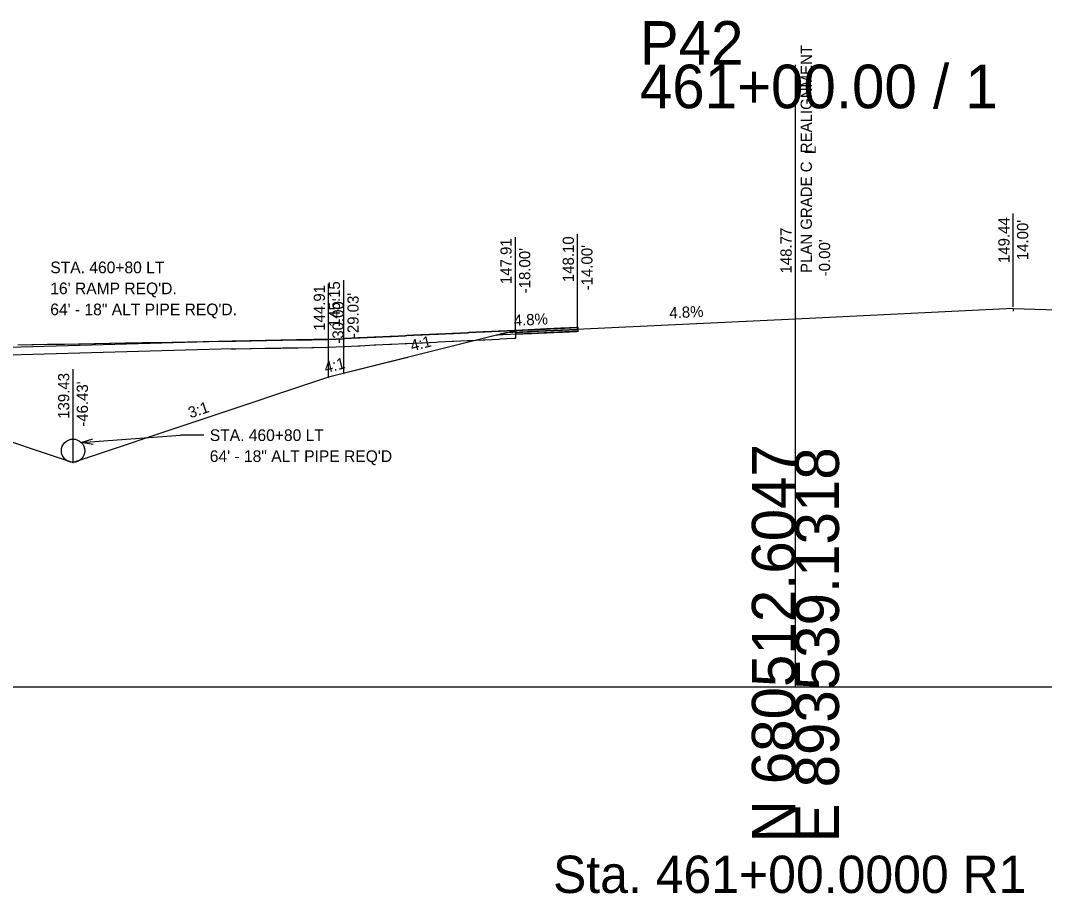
# Model space of a CAD drawing. Extents: x -100 to 4303, y -13 to 10775.
# Drawn here: x 100.2 to 166, y 9486.7 to 9542.8 of the extents above; entities that cross this region are included whole.
import ezdxf

# ---------------------------------------------------------------- set-up
doc = ezdxf.new("R2010")
doc.units = 0
for name, color, linetype in [('_CIVIL_CONSTRUCTION', 7, 'Continuous'), ('ASHPALT_12_5MM1', 7, 'Continuous'), ('CONST_DCH', 7, 'Continuous'), ('CONST_LV3', 7, 'Continuous'), ('Draft_XS_Text', 7, 'Continuous'), ('DTM_P_FINISHED_GRADE', 7, 'Continuous'), ('DTM_TEMP_DROP', 7, 'Continuous'), ('DTM_X_GROUND', 7, 'Continuous'), ('SLOPE_STAKES_FILL', 7, 'Continuous'), ('X_PROFILES_1', 7, 'Continuous'), ('XS_CELL', 7, 'Continuous'), ('XS_P_CRUSHED_STONE', 7, 'Continuous'), ('XS_P_DR_ASPHALT', 7, 'Continuous'), ('XS_P_DR_ASPHALT_B', 7, 'Continuous'), ('XS_P_DR_GRAVEL', 7, 'Continuous'), ('XS_P_DRAINAGE', 7, 'Continuous'), ('XS_P_SHOULDER', 7, 'Continuous'), ('XS_P_TX_CLEARZONE', 7, 'Continuous'), ('XS_P_TX_FS_BS', 7, 'Continuous')]:
    doc.layers.add(name, color=color, linetype=linetype)

msp = doc.modelspace()

# ---------------------------------------------------------------- linework, layer by layer
at = {"layer": 'ASHPALT_12_5MM1'}
for q in [(164, 9524.147), (164, 9524.15)]:
    msp.add_line((164, 9524.317), q, dxfattribs=at)
at = {"layer": 'CONST_LV3'}
for points in [[(100.032, 9521.99), (100.928, 9522.005), (101.032, 9522.007), (101.928, 9522.023), (102.032, 9522.025), (102.928, 9522.04), (103.032, 9522.042), (103.928, 9522.058), (104.032, 9522.06), (104.928, 9522.075), (105.032, 9522.077), (105.928, 9522.093), (106.032, 9522.095), (106.928, 9522.11), (107.032, 9522.112), (107.928, 9522.128), (108.032, 9522.13), (108.928, 9522.145), (109.032, 9522.147), (109.928, 9522.163), (110.032, 9522.165), (110.928, 9522.18), (111.032, 9522.182), (111.928, 9522.198), (112.032, 9522.2), (112.928, 9522.215), (113.032, 9522.217), (113.928, 9522.233), (114.032, 9522.235), (114.928, 9522.25), (115.032, 9522.252), (115.928, 9522.268), (116.032, 9522.27), (116.928, 9522.285), (117.032, 9522.287), (117.928, 9522.303), (118.032, 9522.305), (118.928, 9522.32), (119.032, 9522.322), (119.928, 9522.338), (120.032, 9522.34), (120.928, 9522.383), (121.032, 9522.388), (121.928, 9522.431), (122.032, 9522.436), (122.928, 9522.479), (123.032, 9522.484), (123.928, 9522.527), (124.032, 9522.532), (124.928, 9522.575), (125.032, 9522.58), (125.928, 9522.623), (126.032, 9522.628), (126.928, 9522.671), (127.032, 9522.676), (127.928, 9522.719), (128.032, 9522.724), (128.928, 9522.767), (129.032, 9522.772), (129.928, 9522.815), (130.032, 9522.82), (130.928, 9522.863), (131.032, 9522.868), (131.928, 9522.911), (132.032, 9522.916), (132.928, 9522.959), (133.032, 9522.964), (133.928, 9523.007), (134.032, 9523.012), (134.928, 9523.055), (135.032, 9523.06), (135.928, 9523.103), (136.032, 9523.108)], [(125.084, 9521.177), (120, 9519.906)]]:
    msp.add_lwpolyline(points, dxfattribs=at)
at = {"layer": 'DTM_P_FINISHED_GRADE'}
for points in [[(132.032, 9522.916), (132.928, 9522.959), (133.032, 9522.964), (133.928, 9523.007), (134.032, 9523.012), (134.928, 9523.055), (135.032, 9523.06), (135.928, 9523.103), (136.032, 9523.108)], [(100.032, 9521.99), (100.928, 9522.005), (101.032, 9522.007), (101.928, 9522.023), (102.032, 9522.025), (102.928, 9522.04), (103.032, 9522.042), (103.928, 9522.058), (104.032, 9522.06), (104.928, 9522.075), (105.032, 9522.077), (105.928, 9522.093), (106.032, 9522.095), (106.928, 9522.11), (107.032, 9522.112), (107.928, 9522.128), (108.032, 9522.13), (108.928, 9522.145), (109.032, 9522.147), (109.928, 9522.163), (110.032, 9522.165), (110.928, 9522.18), (111.032, 9522.182), (111.928, 9522.198), (112.032, 9522.2), (112.928, 9522.215), (113.032, 9522.217), (113.928, 9522.233), (114.032, 9522.235), (114.928, 9522.25), (115.032, 9522.252), (115.928, 9522.268), (116.032, 9522.27), (116.928, 9522.285), (117.032, 9522.287), (117.928, 9522.303), (118.032, 9522.305), (118.928, 9522.32), (119.032, 9522.322), (119.928, 9522.338), (120.032, 9522.34), (120.928, 9522.383), (121.032, 9522.388), (121.928, 9522.431), (122.032, 9522.436), (122.928, 9522.479), (123.032, 9522.484), (123.928, 9522.527), (124.032, 9522.532), (124.928, 9522.575), (125.032, 9522.58), (125.928, 9522.623), (126.032, 9522.628), (126.928, 9522.671), (127.032, 9522.676), (127.928, 9522.719), (128.032, 9522.724), (128.928, 9522.767), (129.032, 9522.772), (129.928, 9522.815), (130.032, 9522.82), (130.928, 9522.863), (131.032, 9522.868), (131.928, 9522.911), (132.032, 9522.916)]]:
    msp.add_lwpolyline(points, dxfattribs=at)
at = {"layer": 'DTM_X_GROUND'}
for p, q in [((164, 9524.317), (150.015, 9523.645)), ((164, 9524.317), (168.734, 9524.17)), ((150.015, 9523.645), (131.382, 9522.752))]:
    msp.add_line(p, q, dxfattribs=at)
for points in [[(131.382, 9522.752), (120, 9519.906), (103.57, 9514.43)], [(97.282, 9516.526), (103.57, 9514.43)]]:
    msp.add_lwpolyline(points, dxfattribs=at)
at = {"layer": 'XS_CELL'}
for p, q in [((150, 9500), (150, 9540)), ((150, 9500), (150, 9540)), ((0, 9500), (150, 9500)), ((0, 9500), (150, 9500)), ((150, 9500), (300, 9500)), ((150, 9500), (300, 9500))]:
    msp.add_line(p, q, dxfattribs=at)
at = {"layer": 'XS_P_CRUSHED_STONE'}
for p, q in [((136.032, 9523.108), (134.025, 9523.011)), ((136.032, 9522.817), (136.032, 9523.108)), ((130.794, 9522.606), (132.032, 9522.916)), ((136.032, 9522.858), (130.794, 9522.606)), ((131.113, 9522.717), (131.11, 9522.717)), ((131.11, 9522.717), (131.124, 9522.717)), ((132.037, 9522.916), (132.032, 9522.916)), ((132.032, 9522.916), (132.032, 9522.916)), ((134.032, 9523.012), (132.037, 9522.916)), ((134.037, 9523.012), (134.032, 9523.012)), ((136.032, 9522.816), (136.032, 9522.817))]:
    msp.add_line(p, q, dxfattribs=at)
at = {"layer": 'XS_P_DR_ASPHALT'}
msp.add_lwpolyline([(132.032, 9522.916), (132.032, 9522.791), (132.928, 9522.834), (132.928, 9522.834), (132.928, 9522.834), (133.032, 9522.839), (133.928, 9522.882), (133.928, 9522.882), (133.928, 9522.882), (134.032, 9522.887), (134.928, 9522.93), (135.032, 9522.935), (135.032, 9522.935), (135.032, 9522.935), (135.928, 9522.978), (136.032, 9522.983), (136.032, 9523.108), (135.928, 9523.103), (135.032, 9523.06), (135.032, 9523.06), (135.032, 9523.06), (134.928, 9523.055), (134.032, 9523.012), (133.928, 9523.007), (133.928, 9523.007), (133.928, 9523.007), (133.032, 9522.964), (132.928, 9522.959), (132.928, 9522.959), (132.928, 9522.959), (132.032, 9522.916)], dxfattribs=at)
at = {"layer": 'XS_P_DR_ASPHALT_B'}
msp.add_lwpolyline([(132.032, 9522.791), (132.032, 9522.666), (132.928, 9522.709), (132.928, 9522.709), (132.928, 9522.709), (133.032, 9522.714), (133.928, 9522.757), (133.928, 9522.757), (133.928, 9522.757), (134.032, 9522.762), (134.928, 9522.805), (135.032, 9522.81), (135.032, 9522.81), (135.032, 9522.81), (135.928, 9522.853), (136.032, 9522.858), (136.032, 9522.983), (135.928, 9522.978), (135.032, 9522.935), (135.032, 9522.935), (135.032, 9522.935), (134.928, 9522.93), (134.032, 9522.887), (133.928, 9522.882), (133.928, 9522.882), (133.928, 9522.882), (133.032, 9522.839), (132.928, 9522.834), (132.928, 9522.834), (132.928, 9522.834), (132.032, 9522.791)], dxfattribs=at)
at = {"layer": 'XS_P_DR_GRAVEL'}
for p, q in [((113.805, 9522.231), (-17.707, 9518.498)), ((113.817, 9521.731), (-17.694, 9517.998))]:
    msp.add_line(p, q, dxfattribs=at)
msp.add_lwpolyline([(113.706, 9521.729), (113.928, 9521.733), (114.032, 9521.735), (114.928, 9521.75), (115.032, 9521.752), (115.928, 9521.768), (116.032, 9521.77), (116.928, 9521.785), (117.032, 9521.787), (117.928, 9521.803), (118.032, 9521.805), (118.928, 9521.82), (119.032, 9521.822), (119.928, 9521.838), (120.032, 9521.84), (120.928, 9521.883), (121.032, 9521.888), (121.928, 9521.931), (122.032, 9521.936), (122.928, 9521.979), (123.032, 9521.984), (123.928, 9522.027), (124.032, 9522.032), (124.928, 9522.075), (125.032, 9522.08), (125.928, 9522.123), (126.032, 9522.128), (126.928, 9522.171), (127.032, 9522.176), (127.928, 9522.219), (127.928, 9522.219), (128.032, 9522.224), (128.928, 9522.267), (129.032, 9522.272), (129.928, 9522.315), (130.032, 9522.32), (130.032, 9522.32), (130.928, 9522.363), (131.032, 9522.368), (131.928, 9522.411), (131.928, 9522.411), (132.032, 9522.416), (132.032, 9522.916), (131.928, 9522.911), (131.928, 9522.911), (131.032, 9522.868), (130.928, 9522.863), (130.032, 9522.82), (130.032, 9522.82), (129.928, 9522.815), (129.032, 9522.772), (128.928, 9522.767), (128.032, 9522.724), (127.928, 9522.719), (127.928, 9522.719), (127.032, 9522.676), (126.928, 9522.671), (126.032, 9522.628), (125.928, 9522.623), (125.032, 9522.58), (124.928, 9522.575), (124.032, 9522.532), (123.928, 9522.527), (123.032, 9522.484), (122.928, 9522.479), (122.032, 9522.436), (121.928, 9522.431), (121.032, 9522.388), (120.928, 9522.383), (120.032, 9522.34), (119.928, 9522.338), (119.032, 9522.322), (118.928, 9522.32), (118.032, 9522.305), (117.928, 9522.303), (117.032, 9522.287), (116.928, 9522.285), (116.032, 9522.27), (115.928, 9522.268), (115.032, 9522.252), (114.928, 9522.25), (114.032, 9522.235), (113.928, 9522.233), (113.805, 9522.231)], dxfattribs=at)
at = {"layer": 'XS_P_DRAINAGE'}
for p in [(104.101, 9515.71), (111.984, 9516.182)]:
    msp.add_line(p, (110.484, 9516.182), dxfattribs=at)
msp.add_lwpolyline([(104.862, 9515.579), (104.101, 9515.71), (104.835, 9515.953)], dxfattribs=at)
msp.add_circle((103.57, 9515.18), 0.75, dxfattribs=at)
at = {"layer": 'XS_P_SHOULDER'}
msp.add_lwpolyline([(132.032, 9522.916), (132.043, 9522.916), (136.032, 9523.108)], dxfattribs=at)
at = {"layer": 'XS_P_TX_CLEARZONE'}
for p, q in [((164, 9524.442), (164, 9530.442)), ((164, 9524.442), (164, 9530.442)), ((150, 9523.77), (150, 9529.77)), ((150, 9523.77), (150, 9529.77)), ((150, 9523.77), (150, 9529.77)), ((136, 9523.098), (136, 9529.098)), ((136, 9523.098), (136, 9529.098)), ((136, 9523.098), (136, 9529.098)), ((136, 9523.098), (136, 9529.098)), ((136, 9523.098), (136, 9529.098)), ((132, 9522.906), (132, 9528.906)), ((132, 9522.906), (132, 9528.906)), ((132, 9522.906), (132, 9528.906)), ((132, 9522.906), (132, 9528.906)), ((132, 9522.906), (132, 9528.906)), ((120, 9519.906), (120, 9525.906)), ((120, 9519.906), (120, 9525.906)), ((120.969, 9520.148), (120.969, 9526.148)), ((120.969, 9520.148), (120.969, 9526.148)), ((120.969, 9520.148), (120.969, 9526.148)), ((103.57, 9514.43), (103.57, 9520.43)), ((103.57, 9514.43), (103.57, 9520.43)), ((103.57, 9514.43), (103.57, 9520.43))]:
    msp.add_line(p, q, dxfattribs=at)

# ---------------------------------------------------------------- texts
at = {"layer": '_CIVIL_CONSTRUCTION'}
for height, p in [(0.12, (149.961, 9523.71)), (0.12, (133.961, 9522.942)), (0.12, (135.961, 9523.038)), (0.001, (136.031, 9523.107)), (0.12, (131.039, 9522.647)), (0.001, (131.11, 9522.716)), (0.001, (134.031, 9523.011)), (0.001, (134.036, 9522.335))]:
    msp.add_text('X', height=height, dxfattribs=at).set_placement(p)
at = {"layer": 'CONST_DCH'}
for height, p in [(0.12, (103.531, 9514.37)), (0.001, (103.527, 9514.415))]:
    msp.add_text('X', height=height, dxfattribs=at).set_placement(p)
at = {"layer": 'Draft_XS_Text'}
msp.add_text('Sta. 461+00.0000 R1', height=2.4, dxfattribs=at).set_placement((134.42, 9486.75))
at = {"layer": 'DTM_TEMP_DROP'}
for height, p in [(0.12, (131.961, 9522.846)), (0.001, (132.031, 9522.915))]:
    msp.add_text('X', height=height, dxfattribs=at).set_placement(p)
at = {"layer": 'SLOPE_STAKES_FILL'}
msp.add_text('X', height=0.12, dxfattribs=at).set_placement((119.961, 9519.846))
at = {"layer": 'X_PROFILES_1'}
msp.add_text('X', height=0.12, dxfattribs=at).set_placement((120.93, 9520.088))
at = {"layer": 'XS_CELL'}
for s, p in [('P42', (140, 9540)), ('P42', (140, 9540)), ('461+00.00 / 1', (140, 9537.2)), ('461+00.00 / 1', (140, 9537.2))]:
    msp.add_text(s, height=2.8, dxfattribs=at).set_placement(p)
for s, p in [('N 680512.6047', (150, 9490)), ('N 680512.6047', (150, 9490)), ('E 893539.1318', (152.8, 9490)), ('E 893539.1318', (152.8, 9490))]:
    msp.add_text(s, height=2.8, rotation=90, dxfattribs=at).set_placement(p)
at = {"layer": 'XS_P_DRAINAGE'}
for s, p in [('STA. 460+80 LT', (102.109, 9526.592)), ("16' RAMP REQ'D.", (102.109, 9525.242)), ('64\' - 18" ALT PIPE REQ\'D.', (102.109, 9523.892)), ('STA. 460+80 LT', (112.359, 9515.807)), ('64\' - 18" ALT PIPE REQ\'D', (112.359, 9514.457))]:
    msp.add_text(s, height=0.75, dxfattribs=at).set_placement(p)
at = {"layer": 'XS_P_TX_CLEARZONE'}
for s, p in [('PLAN GRADE C  REALIGNMENT', (151.056, 9526.607)), ('L', (151.306, 9534.252)), ('149.44', (163.76, 9527.246)), ('149.44', (163.76, 9527.246)), ("14.00'", (164.96, 9527.428)), ("14.00'", (164.96, 9527.428)), ('148.77', (149.76, 9526.574)), ('148.77', (149.76, 9526.574)), ('148.77', (149.76, 9526.574)), ('147.91', (131.76, 9525.892)), ('147.91', (131.76, 9525.892)), ('147.91', (131.76, 9525.892)), ('147.91', (131.76, 9525.892)), ('147.91', (131.76, 9525.892)), ('148.10', (135.76, 9526.021)), ('148.10', (135.76, 9526.021)), ('148.10', (135.76, 9526.021)), ('148.10', (135.76, 9526.021)), ('148.10', (135.76, 9526.021)), ("-14.00'", (136.96, 9525.494)), ("-14.00'", (136.96, 9525.494)), ("-14.00'", (136.96, 9525.494)), ("-14.00'", (136.96, 9525.494)), ("-14.00'", (136.96, 9525.494)), ("-0.00'", (152.232, 9526.394)), ("-18.00'", (132.96, 9525.302)), ("-18.00'", (132.96, 9525.302)), ("-18.00'", (132.96, 9525.302)), ("-18.00'", (132.96, 9525.302)), ("-18.00'", (132.96, 9525.302)), ('144.91', (119.76, 9522.892)), ('144.91', (119.76, 9522.892)), ('145.15', (120.729, 9523.134)), ('145.15', (120.729, 9523.134)), ('145.15', (120.729, 9523.134)), ("-29.03'", (121.929, 9522.42)), ("-29.03'", (121.929, 9522.42)), ("-29.03'", (121.929, 9522.42)), ("-30.00'", (120.96, 9522.064)), ("-30.00'", (120.96, 9522.064)), ('139.43', (103.33, 9517.234)), ('139.43', (103.33, 9517.234)), ('139.43', (103.33, 9517.234)), ("-46.43'", (104.53, 9516.724)), ("-46.43'", (104.53, 9516.724)), ("-46.43'", (104.53, 9516.724))]:
    msp.add_text(s, height=0.72, rotation=90, dxfattribs=at).set_placement(p)
at = {"layer": 'XS_P_TX_FS_BS'}
for s, rotation, p in [('4.8%', 2.74809, (141.913, 9523.682)), ('4.8%', 2.74809, (131.913, 9523.202)), ('4:1', 14.20534, (125.357, 9521.568)), ('4:1', 14.03626, (119.818, 9520.17)), ('3:1', 18.43323, (111.109, 9517.259))]:
    msp.add_text(s, height=0.72, rotation=rotation, dxfattribs=at).set_placement(p)

doc.saveas('drawing.dxf')
